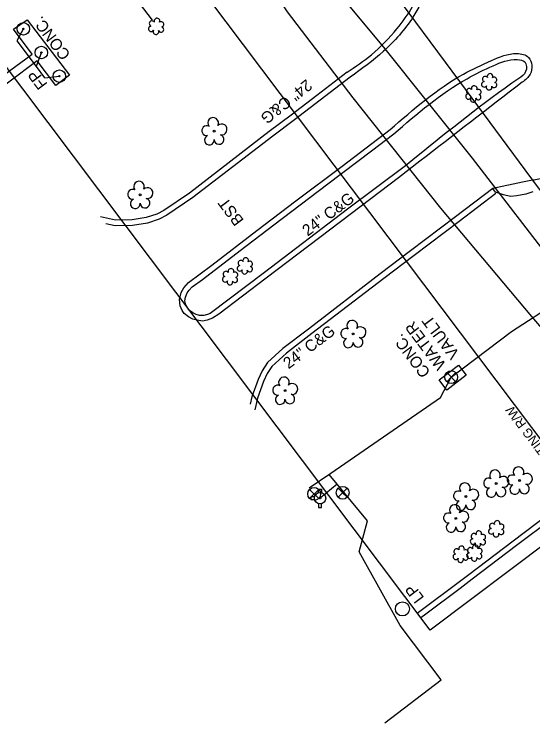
# Model space of a CAD drawing. Extents: x 1262092 to 1264624, y 774970 to 778314.
# Drawn here: x 1264159.5 to 1264340.5, y 774970.4 to 775217.7 of the extents above; entities that cross this region are included whole.
import ezdxf

# ---------------------------------------------------------------- set-up
doc = ezdxf.new("R2010")
doc.units = 0
for name, color, linetype in [('COGO Default Parcel', 7, 'Continuous'), ('Exist Horizontal Alignment Station Label', 7, 'Continuous'), ('Exist Horizontal Alignment Tick Large', 7, 'Continuous'), ('Exist Horizontal Alignment Tick Small', 7, 'Continuous'), ('Exist Other Culture Located Object Leader', 7, 'Continuous'), ('Exist Right of Way Line', 7, 'Continuous'), ('Exist Right of Way Line Text', 7, 'Continuous'), ('Exist Roads Curbs', 7, 'Continuous'), ('Exist Roads EOP', 7, 'Continuous'), ('Exist Roads EOP Other', 7, 'Continuous'), ('Exist Roads EOT', 7, 'Continuous'), ('Exist Utilities Gas UG Line SUE LOS B', 7, 'Continuous'), ('Exist Utilities Other Pole Text', 7, 'Continuous'), ('Exist Utilities Power UG Cable SUE LOS B', 7, 'Continuous'), ('Exist Utilities Telephone UG FO SUE LOS B', 7, 'Continuous'), ('Exist Utilities Water Fire Hydrant CELL', 7, 'Continuous'), ('Exist Utilities Water UG Line SUE LOS B', 7, 'Continuous'), ('Exist Utilities Water Valve CELL', 7, 'Continuous'), ('Prop Horizontal Alignment', 7, 'Continuous'), ('Prop Horizontal Alignment Station Label', 7, 'Continuous'), ('Prop Superelevation Label', 7, 'Continuous'), ('Sheet Data Field CELL', 7, 'Continuous'), ('Sheet Plan CELL', 7, 'Continuous'), ('Sheet Sticker Incomplete CELL', 7, 'Continuous')]:
    doc.layers.add(name, color=color, linetype=linetype)

# ---------------------------------------------------------------- blocks, each defined once
blk = doc.blocks.new('EXIST UTILITIES WATER VALVE')
at = {"layer": 'Exist Utilities Water Valve CELL'}
blk.add_lwpolyline([(0.0315, 0.0315), (-0.0315, -0.0315), (0, 0), (0.0315, -0.0315), (-0.0315, 0.0315)], dxfattribs=at)
blk.add_circle((0, 0), 0.0445, dxfattribs=at)
blk = doc.blocks.new('EXIST UTILITIES WATER FIRE HYDRANT')
at = {"layer": 'Exist Utilities Water Fire Hydrant CELL'}
blk.add_line((0, 0), (0, 0), dxfattribs=at)
for points in [[(-0.01025, 0.03825), (-0.01025, 0.064), (0.01025, 0.064), (0.01025, 0.03775)], [(-0.03825, 0.01025), (-0.064, 0.01025), (-0.064, -0.01025), (-0.03825, -0.01025)], [(-0.01025, -0.03825), (-0.01025, -0.064), (0.01025, -0.064), (0.01025, -0.03775)]]:
    blk.add_lwpolyline(points, dxfattribs=at)
for radius in [0.03954, 0.00485]:
    blk.add_circle((0, 0), radius, dxfattribs=at)

msp = doc.modelspace()

# ---------------------------------------------------------------- linework, layer by layer
at = {"layer": 'COGO Default Parcel'}
for p, q in [((1264304.64, 775002.74), (1263276.19, 776368.79)), ((1264624.2, 775243.33), (1264304.64, 775002.74))]:
    msp.add_line(p, q, dxfattribs=at)
at = {"layer": 'Exist Horizontal Alignment Station Label'}
msp.add_line((1264191.13, 775237.31), (1264207.62, 775215.52), dxfattribs=at)
at = {"layer": 'Exist Horizontal Alignment Tick Large'}
for p, q in [((1264209.08, 775213.23), (1264209.08, 775213.23)), ((1264325.34, 775193.88), (1264325.34, 775193.88)), ((1264319.81, 775189.63), (1264319.81, 775189.63)), ((1264240.05, 775129.66), (1264240.05, 775129.66)), ((1264234.89, 775125.86), (1264234.89, 775125.86)), ((1264327.8, 775037.94), (1264327.8, 775037.94)), ((1264321.41, 775034.36), (1264321.41, 775034.36)), ((1264315.38, 775029.03), (1264315.38, 775029.03)), ((1264320.17, 775029.46), (1264320.17, 775029.46))]:
    msp.add_line(p, q, dxfattribs=at)
for centre, radius, start, end in [((1264207.6, 775214.36), 0.968, 35.8908, 245.4216), ((1264209.31, 775215.27), 0.99, 334.8391, 200.4717), ((1264210.76, 775214.1), 0.929, 284.4567, 126.0861), ((1264207.28, 775212.53), 0.955, 95.1099, 327.9534), ((1264208.96, 775211.55), 0.984, 151.2797, 21.387), ((1264210.72, 775212.3), 0.937, 204.9913, 73.4601), ((1264325.57, 775195.92), 0.99, 334.8391, 200.4717), ((1264323.86, 775195), 0.968, 35.8908, 245.4216), ((1264327.01, 775194.75), 0.929, 284.4567, 126.0861), ((1264320.04, 775191.67), 0.99, 334.8391, 200.4717), ((1264323.54, 775193.17), 0.955, 95.1099, 327.9534), ((1264325.21, 775192.19), 0.984, 151.2797, 21.387), ((1264326.98, 775192.95), 0.937, 204.9913, 73.4601), ((1264318.01, 775188.92), 0.955, 95.1099, 327.9534), ((1264318.33, 775190.76), 0.968, 35.8908, 245.4216), ((1264321.45, 775188.7), 0.937, 204.9913, 73.4601), ((1264321.48, 775190.5), 0.929, 284.4567, 126.0861), ((1264319.68, 775187.94), 0.984, 151.2797, 21.387), ((1264240.28, 775131.7), 0.99, 334.8391, 200.4717), ((1264238.57, 775130.79), 0.968, 35.8908, 245.4216), ((1264241.72, 775130.53), 0.929, 284.4567, 126.0861), ((1264233.4, 775126.99), 0.968, 35.8908, 245.4216), ((1264235.12, 775127.9), 0.99, 334.8391, 200.4717), ((1264236.56, 775126.73), 0.929, 284.4567, 126.0861), ((1264238.25, 775128.96), 0.955, 95.1099, 327.9534), ((1264239.92, 775127.98), 0.984, 151.2797, 21.387), ((1264241.69, 775128.73), 0.937, 204.9913, 73.4601), ((1264233.09, 775125.16), 0.955, 95.1099, 327.9534), ((1264236.52, 775124.93), 0.937, 204.9913, 73.4601), ((1264234.76, 775124.18), 0.984, 151.2797, 21.387), ((1264328.03, 775039.98), 0.99, 334.8391, 200.4717), ((1264326.32, 775039.07), 0.968, 35.8908, 245.4216), ((1264329.47, 775038.81), 0.929, 284.4567, 126.0861), ((1264319.93, 775035.49), 0.968, 35.8908, 245.4216), ((1264321.64, 775036.4), 0.99, 334.8391, 200.4717), ((1264323.08, 775035.23), 0.929, 284.4567, 126.0861), ((1264326, 775037.23), 0.955, 95.1099, 327.9534), ((1264327.67, 775036.25), 0.984, 151.2797, 21.387), ((1264329.44, 775037.01), 0.937, 204.9913, 73.4601), ((1264319.61, 775033.66), 0.955, 95.1099, 327.9534), ((1264323.05, 775033.43), 0.937, 204.9913, 73.4601), ((1264313.9, 775030.15), 0.968, 35.8908, 245.4216), ((1264315.61, 775031.07), 0.99, 334.8391, 200.4717), ((1264318.68, 775030.59), 0.968, 35.8908, 245.4216), ((1264320.4, 775031.5), 0.99, 334.8391, 200.4717), ((1264321.28, 775032.68), 0.984, 151.2797, 21.387), ((1264321.84, 775030.33), 0.929, 284.4567, 126.0861), ((1264313.58, 775028.32), 0.955, 95.1099, 327.9534), ((1264317.02, 775028.1), 0.937, 204.9913, 73.4601), ((1264317.05, 775029.9), 0.929, 284.4567, 126.0861), ((1264318.37, 775028.75), 0.955, 95.1099, 327.9534), ((1264321.8, 775028.53), 0.937, 204.9913, 73.4601), ((1264315.25, 775027.34), 0.984, 151.2797, 21.387), ((1264320.04, 775027.78), 0.984, 151.2797, 21.387)]:
    msp.add_arc(centre, radius, start, end, dxfattribs=at)
at = {"layer": 'Exist Horizontal Alignment Tick Small'}
for p, q in [((1264229.3, 775176.84), (1264229.3, 775176.84)), ((1264203.44, 775154.64), (1264203.44, 775154.64)), ((1264277.81, 775106.08), (1264277.81, 775106.08)), ((1264254, 775086.31), (1264254, 775086.31)), ((1264327.68, 775053.9), (1264327.68, 775053.9)), ((1264335.88, 775054.95), (1264335.88, 775054.95)), ((1264317.14, 775049.4), (1264317.14, 775049.4)), ((1264313.65, 775041.74), (1264313.65, 775041.74))]:
    msp.add_line(p, q, dxfattribs=at)
for centre in [(1264229.3, 775176.84), (1264203.44, 775154.64), (1264277.81, 775106.08), (1264254, 775086.31), (1264327.68, 775053.9), (1264335.88, 775054.95), (1264317.14, 775049.4), (1264313.65, 775041.74)]:
    msp.add_circle(centre, 0.326, dxfattribs=at)
for centre, radius, start, end in [((1264228.91, 775179.71), 1.86, 330.1651, 219.7134), ((1264226.69, 775176.99), 1.73, 62.6636, 279.3457), ((1264231.85, 775177.43), 1.9, 257.1011, 134.1999), ((1264227.6, 775173.72), 1.69, 111.5671, 6.231), ((1264230.97, 775173.94), 1.7, 181.2822, 74.56), ((1264203.05, 775157.51), 1.86, 330.1651, 219.7134), ((1264200.83, 775154.79), 1.73, 62.6636, 279.3457), ((1264205.99, 775155.22), 1.9, 257.1011, 134.1999), ((1264201.74, 775151.52), 1.69, 111.5671, 6.231), ((1264205.11, 775151.74), 1.7, 181.2822, 74.56), ((1264277.43, 775108.96), 1.86, 330.1651, 219.7134), ((1264275.21, 775106.24), 1.73, 62.6636, 279.3457), ((1264280.36, 775106.67), 1.9, 257.1011, 134.1999), ((1264276.11, 775102.96), 1.69, 111.5671, 6.231), ((1264279.48, 775103.19), 1.7, 181.2822, 74.56), ((1264253.62, 775089.18), 1.86, 330.1651, 219.7134), ((1264251.4, 775086.46), 1.73, 62.6636, 279.3457), ((1264256.55, 775086.9), 1.9, 257.1011, 134.1999), ((1264252.3, 775083.19), 1.69, 111.5671, 6.231), ((1264255.68, 775083.41), 1.7, 181.2822, 74.56), ((1264327.3, 775056.77), 1.86, 330.1651, 219.7134), ((1264335.49, 775057.83), 1.86, 330.1651, 219.7134), ((1264330.23, 775054.48), 1.9, 257.1011, 134.1999), ((1264333.27, 775055.11), 1.73, 62.6636, 279.3457), ((1264338.43, 775055.54), 1.9, 257.1011, 134.1999), ((1264316.76, 775052.27), 1.86, 330.1651, 219.7134), ((1264325.08, 775054.05), 1.73, 62.6636, 279.3457), ((1264334.18, 775051.83), 1.69, 111.5671, 6.231), ((1264337.55, 775052.05), 1.7, 181.2822, 74.56), ((1264314.54, 775049.55), 1.73, 62.6636, 279.3457), ((1264319.69, 775049.99), 1.9, 257.1011, 134.1999), ((1264325.98, 775050.78), 1.69, 111.5671, 6.231), ((1264329.36, 775051), 1.7, 181.2822, 74.56), ((1264313.27, 775044.62), 1.86, 330.1651, 219.7134), ((1264315.44, 775046.28), 1.69, 111.5671, 6.231), ((1264318.82, 775046.5), 1.7, 181.2822, 74.56), ((1264311.05, 775041.9), 1.73, 62.6636, 279.3457), ((1264316.2, 775042.33), 1.9, 257.1011, 134.1999), ((1264311.95, 775038.62), 1.69, 111.5671, 6.231), ((1264315.32, 775038.84), 1.7, 181.2822, 74.56)]:
    msp.add_arc(centre, radius, start, end, dxfattribs=at)
at = {"layer": 'Exist Other Culture Located Object Leader'}
msp.add_line((1264175.24, 775195.96), (1264170.22, 775195.31), dxfattribs=at)
for points in [[(1264162.64, 775212.47), (1264160.35, 775208.37), (1264167.09, 775199.41)], [(1264168.97, 775204.45), (1264167.09, 775199.41), (1264170.1, 775195.42)]]:
    msp.add_lwpolyline(points, dxfattribs=at)
at = {"layer": 'Exist Right of Way Line'}
msp.add_line((1263350.65, 776386.89), (1264378.08, 775022.83), dxfattribs=at)
at = {"layer": 'Exist Roads Curbs'}
for points in [[(1264275.63, 775197.37), (1264265.1, 775189.23), (1264256.11, 775182.39), (1264248.52, 775176.68), (1264220.64, 775155.24), (1264211.72, 775149.19), (1264209.24, 775147.92), (1264205.56, 775146.66), (1264200.65, 775145.85), (1264194.88, 775145.84), (1264189.63, 775146.98)], [(1264299.92, 775167.84), (1264295.99, 775164.73), (1264275.84, 775149.64), (1264246.8, 775127.58), (1264227.83, 775113.19), (1264226.98, 775112.85), (1264225.69, 775112.54), (1264224.19, 775112.56), (1264222.98, 775112.9), (1264221.8, 775113.43), (1264220.71, 775114.24), (1264220.03, 775115.05), (1264219.35, 775116.25), (1264219.04, 775117.64), (1264219.27, 775118.96), (1264219.83, 775120.42), (1264220.49, 775121.37), (1264221.63, 775122.52), (1264225.14, 775125.12), (1264238.38, 775135.17), (1264250.13, 775144.2), (1264268.91, 775158.41), (1264284.16, 775169.97), (1264291.94, 775175.89)], [(1264327.6, 775155.1), (1264314.72, 775145.36), (1264299.04, 775133.49), (1264288.48, 775125.43), (1264263.37, 775106.22), (1264254.57, 775099.41), (1264249.37, 775094.76), (1264247.8, 775092.28), (1264246.45, 775089.45), (1264244.38, 775083.63), (1264243.45, 775079.56)], [(1264300.15, 775008.68), (1264301.96, 775010.02), (1264313.91, 775018.98), (1264318.12, 775022.19), (1264333.63, 775033.94), (1264346.06, 775043.34), (1264363.09, 775056.09), (1264371.46, 775062.28), (1264386.59, 775042.09), (1264397.05, 775027.94)]]:
    msp.add_lwpolyline(points, dxfattribs=at)
for points in [[(1264275.63, 775197.37), (1264284.14, 775203.51), (1264293.07, 775212.59), (1264298.49, 775220.32), (1264302.28, 775231.1), (1264302.48, 775238.27), (1264302.34, 775239.8)], [(1264291.94, 775175.89), (1264317.53, 775195.15), (1264326.66, 775199.67), (1264335.07, 775201.82), (1264337.66, 775201.04), (1264337.98, 775197.61), (1264335.58, 775195.2), (1264299.92, 775167.84)]]:
    msp.add_spline(points, degree=3, dxfattribs=at)
at = {"layer": 'Exist Roads EOP'}
msp.add_line((1264336.92, 775159), (1264326.53, 775156.81), dxfattribs=at)
for points in [[(1264295.65, 775264.58), (1264303.87, 775248.69), (1264303.27, 775226.35), (1264298.63, 775216.67), (1264288.35, 775204.7), (1264276.75, 775195.69)], [(1264290.7, 775177.4), (1264316.28, 775196.76), (1264326.03, 775201.48), (1264334.93, 775203.92), (1264339.02, 775202.54), (1264339.57, 775196.77), (1264336.79, 775193.88), (1264301.04, 775166.33)]]:
    msp.add_spline(points, degree=3, dxfattribs=at)
at = {"layer": 'Exist Roads EOP Other'}
for points in [[(1264276.75, 775195.69), (1264266.29, 775187.65), (1264257.3, 775180.81), (1264249.72, 775175.1), (1264221.8, 775153.64), (1264212.73, 775147.49), (1264210.02, 775146.09), (1264206.04, 775144.73), (1264200.81, 775143.87), (1264194.67, 775143.86), (1264191.47, 775144.55)], [(1264301.04, 775166.33), (1264293.55, 775160.6), (1264277.15, 775148.14), (1264247.4, 775125.56), (1264230.85, 775113.02), (1264228.69, 775111.61), (1264226.87, 775110.88), (1264225.23, 775110.6), (1264223.38, 775110.84), (1264221.78, 775111.3), (1264220.32, 775112.05), (1264218.78, 775113.26), (1264218.08, 775114.29), (1264217.37, 775115.87), (1264217.18, 775118.09), (1264217.7, 775120.56), (1264218.63, 775122.22), (1264220.33, 775123.99), (1264228.4, 775130.14), (1264244.2, 775142.14), (1264257.81, 775152.5), (1264273.96, 775164.62), (1264290.7, 775177.4)], [(1264326.53, 775156.81), (1264313.5, 775146.97), (1264297.82, 775135.09), (1264287.26, 775127.02), (1264262.14, 775107.81), (1264253.28, 775100.96), (1264247.83, 775096.07), (1264246.04, 775093.25), (1264244.59, 775090.22), (1264242.45, 775084.2), (1264241.85, 775081.57)], [(1264340.53, 775155.63), (1264338.09, 775154.89), (1264334.86, 775154.31), (1264332.74, 775154.08), (1264330.26, 775154.66), (1264327.44, 775155.61), (1264326.53, 775156.81)], [(1264301.4, 775007.11), (1264303.16, 775008.41), (1264315.12, 775017.38), (1264319.33, 775020.59), (1264334.84, 775032.34), (1264347.27, 775041.74), (1264364.29, 775054.47), (1264371.05, 775059.47), (1264384.98, 775040.89), (1264395.46, 775026.71)]]:
    msp.add_lwpolyline(points, dxfattribs=at)
at = {"layer": 'Exist Roads EOT'}
msp.add_spline([(1264393.68, 775134.37), (1264373.52, 775154.13), (1264350.12, 775160.74), (1264341.47, 775159.89), (1264336.92, 775159)], degree=3, dxfattribs=at)
at = {"layer": 'Exist Utilities Gas UG Line SUE LOS B'}
msp.add_circle((1264294.96, 775010.17), 2.46, dxfattribs=at)
at = {"layer": 'Exist Utilities Power UG Cable SUE LOS B'}
msp.add_lwpolyline([(1264395.36, 775040.74), (1264370.8, 775076.36), (1264340.19, 775112.15), (1264308.39, 775149.99), (1264277.8, 775188.45), (1264254.82, 775218.46), (1264230.51, 775255.61), (1264208, 775290.17), (1264185.34, 775318.09), (1264158.04, 775354.59), (1264133.61, 775386.92), (1264107.25, 775423.32), (1264089.56, 775447.66), (1264061.08, 775477.65), (1264037.85, 775505.73), (1264032.45, 775511.96), (1264026.57, 775514.09), (1263970.61, 775511.19)], dxfattribs=at)
at = {"layer": 'Exist Utilities Telephone UG FO SUE LOS B'}
msp.add_lwpolyline([(1264412.43, 775054.27), (1264383.09, 775084.33), (1264350.27, 775127.37), (1264319.47, 775167.42), (1264288.52, 775206.2), (1264253.33, 775248.38), (1264233.02, 775276.08), (1264197.49, 775318.53), (1264165.2, 775359.15), (1264131.6, 775400.04), (1264102.3, 775438.18), (1264079.45, 775463.73), (1264046.01, 775506.17), (1264034.16, 775523.07), (1264026.26, 775546.1), (1264015.26, 775566.11), (1263989.3, 775607.52), (1263955.25, 775658.94), (1263921.26, 775710.27), (1263888.91, 775754.45), (1263860.31, 775793.96), (1263832.43, 775832.72), (1263818.26, 775866.25), (1263816.28, 775877)], dxfattribs=at)
at = {"layer": 'Exist Utilities Water UG Line SUE LOS B'}
msp.add_line((1264272.17, 775053.69), (1264266.23, 775048.78), dxfattribs=at)
for points in [[(1264262.47, 775052.4), (1264270.03, 775057.49), (1264308.25, 775083.86), (1264311.99, 775091.01), (1264333.07, 775106.94), (1264365.39, 775127.89), (1264356.78, 775138.68), (1264342.07, 775157.58), (1264315.02, 775194.18), (1264289.27, 775228.94), (1264261.35, 775265.49), (1264234.66, 775298.88), (1264204.95, 775340.41), (1264179.39, 775376.51), (1264153.98, 775411.4), (1264121.66, 775450.17), (1264092.98, 775486.7), (1264069.57, 775517.58), (1264043.23, 775551.19), (1264018.68, 775582.59), (1263995.06, 775614.62), (1263975.68, 775643.74), (1263951.8, 775677.27), (1263925.33, 775714.09)], [(1264288.87, 774970.4), (1264308.55, 774985.35), (1264294.24, 775004.35), (1264279.88, 775030.06), (1264282.74, 775040.9), (1264269.45, 775056.99)]]:
    msp.add_lwpolyline(points, dxfattribs=at)
at = {"layer": 'Prop Horizontal Alignment Station Label'}
for centre, radius in [((1264162.69, 775212.54), 2.18), ((1264162.69, 775212.54), 0.24), ((1264168.96, 775204.26), 2.18), ((1264168.96, 775204.26), 0.24), ((1264175.24, 775196.03), 2.18), ((1264175.24, 775196.03), 0.24)]:
    msp.add_circle(centre, radius, dxfattribs=at)
at = {"layer": 'Prop Superelevation Label'}
msp.add_lwpolyline([(1264153.9, 775195), (1264156.1, 775196.66), (1264165.77, 775203.68), (1264159.27, 775212.41), (1264164.02, 775215.69), (1264178.73, 775196.36), (1264173.98, 775192.79), (1264167.44, 775201.42), (1264157.56, 775193.98), (1264155.72, 775192.55)], dxfattribs=at)
msp.add_lwpolyline([(1264314.52, 775095.2), (1264317.24, 775091.65), (1264310.53, 775086.51), (1264307.81, 775090.07)], close=True, dxfattribs=at)

# ---------------------------------------------------------------- block references
at = {"layer": 'Exist Utilities Water Fire Hydrant CELL', "xscale": 50, "yscale": 50}
msp.add_blockref('EXIST UTILITIES WATER FIRE HYDRANT', (1264266.23, 775048.78), dxfattribs=at)
at = {"layer": 'Exist Utilities Water Valve CELL', "xscale": 50, "yscale": 50}
for p in [(1264311.99, 775091.01), (1264264.17, 775050.29), (1264274.11, 775050.66)]:
    msp.add_blockref('EXIST UTILITIES WATER VALVE', p, dxfattribs=at)

# ---------------------------------------------------------------- texts
at = {"layer": 'Exist Right of Way Line Text'}
msp.add_text('EXISTING R/W', height=3.2, rotation=126.9874, dxfattribs=at).set_placement((1264351.08, 775057.78))
at = {"layer": 'Exist Utilities Other Pole Text'}
msp.add_text('LP', height=4, rotation=126.9746, dxfattribs=at).set_placement((1264302.73, 775014.04))
at = {"layer": 'Prop Horizontal Alignment'}
msp.add_text('BST', height=4, rotation=126.9874, dxfattribs=at).set_placement((1264239.8, 775145.74))
msp.add_text('BST', height=4, rotation=126.9874, dxfattribs=at).set_placement((1264239.8, 775145.74))
at = {"layer": 'Sheet Data Field CELL'}
for s, p in [('CONC.', (1264179.33, 775203.56)), ('WATER', (1264310.42, 775095.42)), ('VAULT', (1264315.11, 775099.16)), ('CONC.', (1264304.94, 775092.72))]:
    msp.add_text(s, height=4, rotation=126.9746, dxfattribs=at).set_placement(p)
at = {"layer": 'Sheet Plan CELL'}
msp.add_text('FP', height=4, rotation=126.9746, dxfattribs=at).set_placement((1264171.26, 775193.26))
at = {"layer": 'Sheet Sticker Incomplete CELL'}
for rotation, p in [(218.489, (1264261.46, 775195.16)), (37.1161, (1264261.91, 775140.01)), (37.1161, (1264255.23, 775093.7))]:
    msp.add_text('24" C&G', height=4, rotation=rotation, dxfattribs=at).set_placement(p)

doc.saveas('drawing.dxf')
